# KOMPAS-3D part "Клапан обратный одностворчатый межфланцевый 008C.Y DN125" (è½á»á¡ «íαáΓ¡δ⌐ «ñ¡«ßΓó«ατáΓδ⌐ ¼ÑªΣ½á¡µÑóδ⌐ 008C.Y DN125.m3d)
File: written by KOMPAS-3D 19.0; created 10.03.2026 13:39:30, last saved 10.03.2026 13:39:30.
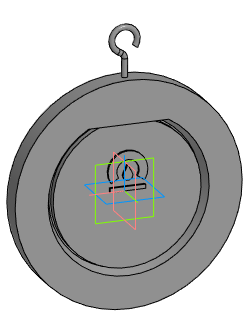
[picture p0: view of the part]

Document properties: Автор: Евгений; Полное имя файла: E:\Dendor\3D для проектировщиков\5.1 Тип 008C. Клапан обратный одностворчатый межфланцевый\stp_Клапан обратный одностворчатый межфланцевый 008C.Y\Клапан обратный одностворчатый межфланцевый 008C.Y DN125.m3d

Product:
- Part/product: Клапан обратный одностворчатый межфланцевый 008C.Y DN125

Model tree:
1. Операция без истории:1  (labels: Клапан обратный одностворчатый межфланцевый 008C.Y DN125)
